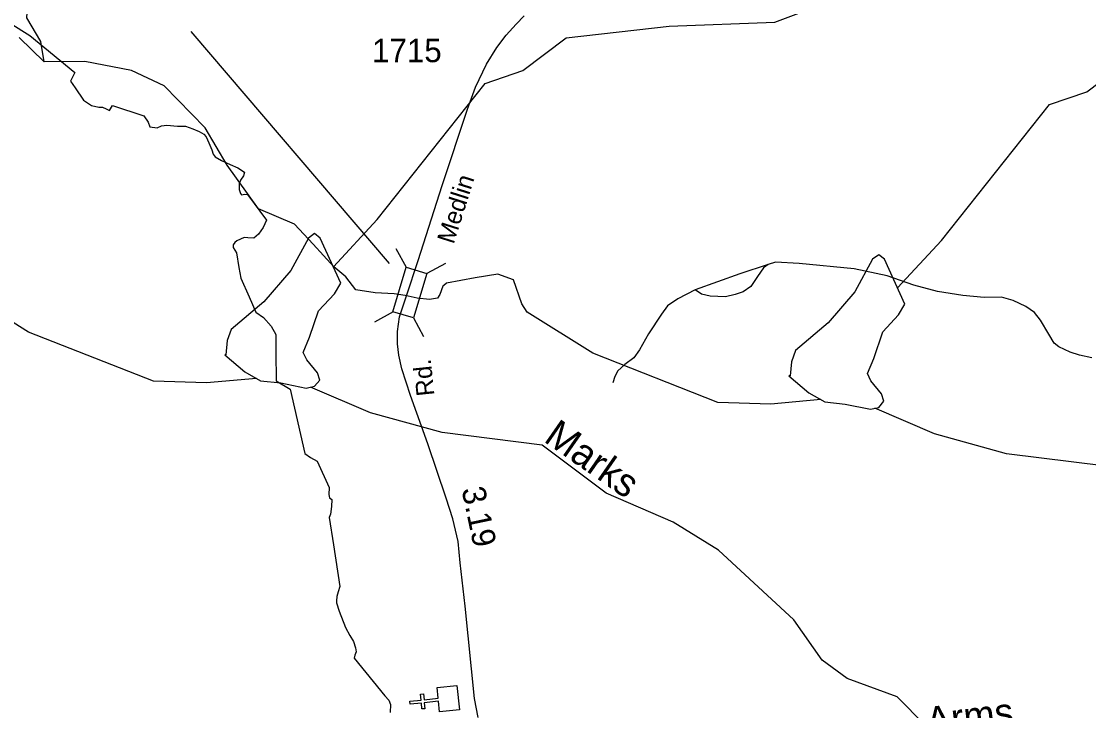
# Model space of a CAD drawing. Extents: x 2169602 to 2449496, y 721995 to 810662.
# Drawn here: x 2414228 to 2419932, y 774064 to 777745 of the extents above; entities that cross this region are included whole.
import ezdxf

# ---------------------------------------------------------------- set-up
doc = ezdxf.new("R2010")
doc.units = 0
doc.layers.add('Default', color=7, linetype='Continuous')

msp = doc.modelspace()

# ---------------------------------------------------------------- linework, layer by layer
at = {"layer": 'Default'}
for p, q in [((2416196, 776451.4), (2415136, 777690.2)), ((2416229.8, 776531.3), (2416283.7, 776431.8)), ((2416494.2, 776452.8), (2416394.7, 776398.9)), ((2416215.2, 776193.6), (2416115.7, 776139.6)), ((2416323.7, 776161.4), (2416377.6, 776061.9))]:
    msp.add_line(p, q, dxfattribs=at)
for points in [[(2414349.6, 777529), (2414332.6, 777637.6), (2414256.5, 777763.8), (2414272.5, 778012.8), (2414362.6, 778237.3), (2414461.6, 778356.6), (2414509.6, 778680.4), (2414616.6, 778888.2), (2414620.5, 779737.6), (2414517.6, 780264.6), (2414507.5, 780589.6), (2414473.5, 780672.3), (2414480.7, 780829.6), (2414554.5, 781080.6), (2414578.5, 781280.3), (2414741.5, 781896.9), (2414823.5, 782131.4), (2414989.6, 782324.8), (2414988.6, 782406.8), (2414863.5, 782448.8), (2414821.7, 782498.8), (2414842.6, 783223.4), (2414880.6, 783881.9), (2414987.6, 784096.3)], [(2416907.7, 777482.1), (2417139.6, 777657.8), (2417689.5, 777718.8), (2418255.7, 777740), (2418588.5, 777867.7), (2418778.6, 778034.4), (2419160.6, 778295.6), (2419359.7, 778504.7), (2419467.5, 778571.4), (2420095.6, 779408.2)], [(2416286.1, 776278.8), (2416349, 776467.3), (2416476.1, 776869.4), (2416613.2, 777277.1), (2416654.6, 777393.5), (2416713.2, 777516.4), (2416768.9, 777606.4), (2416818.9, 777672.1), (2416871.7, 777730.6), (2416914.6, 777774.9)], [(2414168, 777735.5), (2414273.7, 777670.1), (2414512.7, 777471.6), (2414489.5, 777426.2), (2414515.5, 777391), (2414559.5, 777324.1), (2414602.7, 777295.7), (2414641.2, 777286.9), (2414661.7, 777287.3), (2414680.5, 777278.1), (2414699, 777269.7), (2414715, 777296.4), (2414881.5, 777239.9), (2414906, 777206.3), (2414915, 777182.7), (2414953.5, 777177.1), (2414976.5, 777187.1), (2415005.2, 777190.2), (2415062.2, 777186.2), (2415105.5, 777185), (2415144.5, 777171), (2415178.5, 777156.9), (2415202.5, 777143.4), (2415215.7, 777128.6), (2415229.2, 777095.7), (2415245, 777059.3), (2415253.5, 777036.5), (2415264.5, 777021.3), (2415296.7, 777001.7), (2415344.5, 776980.1)], [(2414168, 777735.5), (2414273.7, 777670.1), (2414512.7, 777471.6), (2414489.5, 777426.2), (2414515.5, 777391), (2414559.5, 777324.1), (2414602.7, 777295.7), (2414641.2, 777286.9), (2414661.7, 777287.3), (2414680.5, 777278.1), (2414699, 777269.7), (2414715, 777296.4), (2414881.5, 777239.9), (2414906, 777206.3), (2414915, 777182.7), (2414953.5, 777177.1), (2414976.5, 777187.1), (2415005.2, 777190.2), (2415062.2, 777186.2), (2415105.5, 777185), (2415144.5, 777171), (2415178.5, 777156.9), (2415202.5, 777143.4), (2415215.7, 777128.6), (2415229.2, 777095.7), (2415245, 777059.3), (2415253.5, 777036.5), (2415264.5, 777021.3), (2415296.7, 777001.7), (2415344.5, 776980.1)], [(2414215.4, 777658.1), (2414349.6, 777529)], [(2418500.9, 775725.4), (2418233.5, 775701.3), (2417950.5, 775710.4), (2417282.5, 775973.3), (2416932.1, 776192.1), (2416902.4, 776236.6), (2416857.9, 776365.3), (2416773.8, 776395), (2416654, 776375.5), (2416501, 776346.6), (2416485.5, 776334.5), (2416479.7, 776330.9), (2416464.3, 776286.8), (2416452.2, 776267.5), (2416408.7, 776259), (2416342.5, 776266.1), (2416278.4, 776280.4), (2416221, 776289.4), (2416118, 776296.1), (2416014.9, 776311.8), (2415962.6, 776380.1), (2415898.3, 776434.6), (2415787.4, 776554.9), (2415687.6, 776661.9), (2415495.4, 776744.6), (2415327.5, 776977.7), (2415209.6, 777176.8), (2414991.4, 777401.1), (2414816.5, 777483.4), (2414566.6, 777531.1), (2414349.6, 777529)], [(2419923.5, 777369.3), (2420155.4, 777545)], [(2415895.3, 776434.2), (2416129.5, 776687.8), (2416707.6, 777414.1), (2416907.7, 777482.1)], [(2418911.1, 776321.4), (2419145.3, 776574.9), (2419723.4, 777301.2), (2419923.5, 777369.3)], [(2415344.5, 776980.1), (2415384.5, 776963.2), (2415421.2, 776940.6), (2415414.5, 776920.4), (2415399.7, 776896.4), (2415392, 776877.6), (2415392, 776848), (2415398.7, 776825.2), (2415404, 776818.8), (2415422.5, 776822), (2415435.7, 776820.4), (2415538, 776683.5), (2415520.2, 776644.3), (2415494.5, 776609.1), (2415470.2, 776587.9), (2415438.7, 776588.3), (2415418.7, 776590.3), (2415398.2, 776581.9), (2415379.5, 776573.2), (2415368.7, 776563.6), (2415359, 776551.2), (2415359.5, 776537.6), (2415368.7, 776523.6), (2415377, 776509.6), (2415390, 776430.3), (2415400, 776374.3), (2415445.2, 776274.7), (2415480.5, 776191.9), (2415521.7, 776163), (2415563.5, 776117.8), (2415587.5, 776072.9), (2415588.5, 775979.4), (2415590.2, 775826.1), (2415664.7, 775781.7), (2415743.2, 775436.7), (2415773.5, 775416.7), (2415809.2, 775396.3), (2415873.2, 775255.5), (2415871, 775218.2), (2415875.2, 775201.1), (2415887.7, 775191.4), (2415885.7, 775154.6), (2415879.2, 775112.6), (2415873.2, 775095.9), (2415896, 774949.8), (2415929.2, 774727.5), (2415921.2, 774698.5), (2415913.7, 774674.1), (2415913, 774651.2), (2415912.7, 774640.1), (2415925.7, 774595.6), (2415959.7, 774508.1), (2415984.2, 774465.2), (2416003.7, 774433.6), (2416014.2, 774398.8), (2416017, 774378), (2416009.7, 774361.2), (2416007, 774343.6), (2416171, 774143.9), (2416191.7, 774119.9), (2416201, 774097.6), (2416199, 774053.6)], [(2415344.5, 776980.1), (2415384.5, 776963.2), (2415421.2, 776940.6), (2415414.5, 776920.4), (2415399.7, 776896.4), (2415392, 776877.6), (2415392, 776848), (2415398.7, 776825.2), (2415404, 776818.8), (2415422.5, 776822), (2415435.7, 776820.4), (2415538, 776683.5), (2415520.2, 776644.3), (2415494.5, 776609.1), (2415470.2, 776587.9), (2415438.7, 776588.3), (2415418.7, 776590.3), (2415398.2, 776581.9), (2415379.5, 776573.2), (2415368.7, 776563.6), (2415359, 776551.2), (2415359.5, 776537.6), (2415368.7, 776523.6), (2415377, 776509.6), (2415390, 776430.3), (2415400, 776374.3), (2415445.2, 776274.7), (2415480.5, 776191.9), (2415521.7, 776163), (2415563.5, 776117.8), (2415587.5, 776072.9), (2415588.5, 775979.4), (2415590.2, 775826.1), (2415664.7, 775781.7), (2415743.2, 775436.7), (2415773.5, 775416.7), (2415809.2, 775396.3), (2415873.2, 775255.5), (2415871, 775218.2), (2415875.2, 775201.1), (2415887.7, 775191.4), (2415885.7, 775154.6), (2415879.2, 775112.6), (2415873.2, 775095.9), (2415896, 774949.8), (2415929.2, 774727.5), (2415921.2, 774698.5), (2415913.7, 774674.1), (2415913, 774651.2), (2415912.7, 774640.1), (2415925.7, 774595.6), (2415959.7, 774508.1), (2415984.2, 774465.2), (2416003.7, 774433.6), (2416014.2, 774398.8), (2416017, 774378), (2416009.7, 774361.2), (2416007, 774343.6), (2416171, 774143.9), (2416191.7, 774119.9), (2416201, 774097.6), (2416199, 774053.6)], [(2415934.7, 776347.7), (2415825.3, 776587.9), (2415795.2, 776612), (2415762.1, 776587.9), (2415667.3, 776414.5), (2415524.1, 776247.7), (2415349.3, 776100.2), (2415328.2, 776040), (2415321, 775965.1), (2415314.9, 775965.1), (2415421.6, 775874.4), (2415506, 775826.3), (2415614.4, 775814.2), (2415750, 775787.1), (2415795.2, 775796.2), (2415822.3, 775829.3), (2415810.3, 775868.4), (2415753, 775937.7), (2415734.2, 775977.3), (2415768.1, 776058.1), (2415816.3, 776199.6), (2415900.7, 776289.9), (2415934.7, 776347.7)], [(2418950.5, 776234.8), (2418841.2, 776475.1), (2418811, 776499.2), (2418777.9, 776475.1), (2418683.2, 776301.6), (2418539.9, 776134.9), (2418365.1, 775987.4), (2418344.1, 775927.2), (2418336.8, 775852.3), (2418330.7, 775852.3), (2418437.5, 775761.6), (2418521.8, 775713.4), (2418630.3, 775701.4), (2418765.8, 775674.3), (2418811, 775683.3), (2418838.2, 775716.4), (2418826.1, 775755.6), (2418768.9, 775824.8), (2418750, 775864.4), (2418783.9, 775945.2), (2418832.1, 776086.7), (2418916.5, 776177.1), (2418950.5, 776234.8)], [(2418219.1, 776447.4), (2418194, 776428.7), (2418161.7, 776382), (2418127.6, 776329.9), (2418086.3, 776301.1), (2418043.2, 776286.8), (2417991.1, 776274.2), (2417910.3, 776277.8), (2417863.6, 776288.6), (2417829.5, 776311.9)], [(2418219.1, 776447.4), (2418068.3, 776396.3), (2417829.5, 776311.9)], [(2419948.8, 775949.1), (2419884.1, 775961.7), (2419833.8, 775977.9), (2419772.7, 776006.6), (2419747.6, 776026.3), (2419718.9, 776074.8), (2419675.8, 776150.3), (2419643.4, 776189.8), (2419596.7, 776222.1), (2419528.5, 776254.4), (2419467.4, 776272.4), (2419374, 776270.6), (2419259.1, 776281.4), (2419124.4, 776302.9), (2418998.7, 776337.1), (2418855, 776385.5), (2418679, 776423.3), (2418384.4, 776452), (2418258.7, 776459.2), (2418219.1, 776447.4)], [(2415485, 775838.2), (2415217.6, 775814.2), (2414934.7, 775823.2), (2414266.6, 776086.1), (2413916.3, 776304.9)], [(2416668.9, 774027.8), (2416650.4, 774129.9), (2416600.4, 774622), (2416573.2, 774854.1), (2416561.8, 774968.3), (2416533.2, 775089), (2416499, 775199), (2416400.4, 775488.2), (2416307.6, 775746.7), (2416261.9, 775888.9), (2416244.7, 775963.1), (2416237.6, 776023.1), (2416237.6, 776088.8), (2416249, 776167.4), (2416286.1, 776278.8)], [(2417829.5, 776311.9), (2417736.1, 776263.4), (2417682.2, 776225.7), (2417649.9, 776180.8), (2417579.8, 776076.6), (2417531.3, 775990.4), (2417500.8, 775949.1), (2417454.1, 775913.2), (2417416.4, 775879.1), (2417400.2, 775848.5), (2417389.4, 775814.4)], [(2421758.5, 774102.9), (2421449.5, 774142), (2421074.5, 774241.5), (2420807.5, 774246.9), (2420358.5, 774095.4), (2419900.6, 773999.8), (2419193.6, 773922.3), (2419059.5, 773987.3), (2418909.6, 774138.1), (2418641.6, 774235.3), (2418507.5, 774333.2), (2418356.5, 774549.5), (2417954.4, 774921.9), (2417712.5, 775071.1), (2417353.7, 775226), (2417010.6, 775482.4), (2416476.7, 775549), (2416093.6, 775655.2), (2415773.6, 775791.8)], [(2424774.4, 773990.1), (2424465.4, 774029.1), (2424090.3, 774128.7), (2423823.3, 774134.1), (2423374.3, 773982.6), (2422916.4, 773886.9), (2422209.4, 773809.5), (2422075.3, 773874.5), (2421925.4, 774025.2), (2421657.4, 774122.5), (2421523.3, 774220.4), (2421372.4, 774436.7), (2420970.3, 774809.1), (2420728.3, 774958.3), (2420369.5, 775113.2), (2420026.4, 775369.6), (2419492.5, 775436.2), (2419109.4, 775542.4), (2418789.5, 775679)]]:
    msp.add_lwpolyline(points, dxfattribs=at)
for points in [[(2416394.7, 776398.9), (2416324.2, 776161.2), (2416213.2, 776194.2), (2416283.7, 776431.8)], [(2416463.1, 774057.4), (2416457.3, 774114.1), (2416381.5, 774106.4), (2416384.7, 774074.6), (2416368.8, 774073), (2416365.6, 774104.8), (2416305.8, 774098.8), (2416304.2, 774114.7), (2416364, 774120.8), (2416360.8, 774152.6), (2416376.7, 774154.2), (2416379.9, 774122.4), (2416455.7, 774130), (2416450, 774187.4), (2416555.9, 774198.1), (2416569, 774068.2)]]:
    msp.add_lwpolyline(points, close=True, dxfattribs=at)

# ---------------------------------------------------------------- texts
msp.add_text('1715', height=125, dxfattribs=at).set_placement((2416102.5, 777527.2))
for s, height, rotation, p in [('Medlin', 95, 72.4735, (2416538.1, 776551.6)), ('Rd.', 95, 95.8871, (2416435.7, 775748.6)), ('Marks', 150, 325.1331, (2417014, 775504.6)), ('3.19', 125, 281.8598, (2416580, 775247)), ('Arms', 150, 6.6925, (2419072.9, 773932.4))]:
    msp.add_text(s, height=height, rotation=rotation, dxfattribs=at).set_placement(p)

doc.saveas('drawing.dxf')
